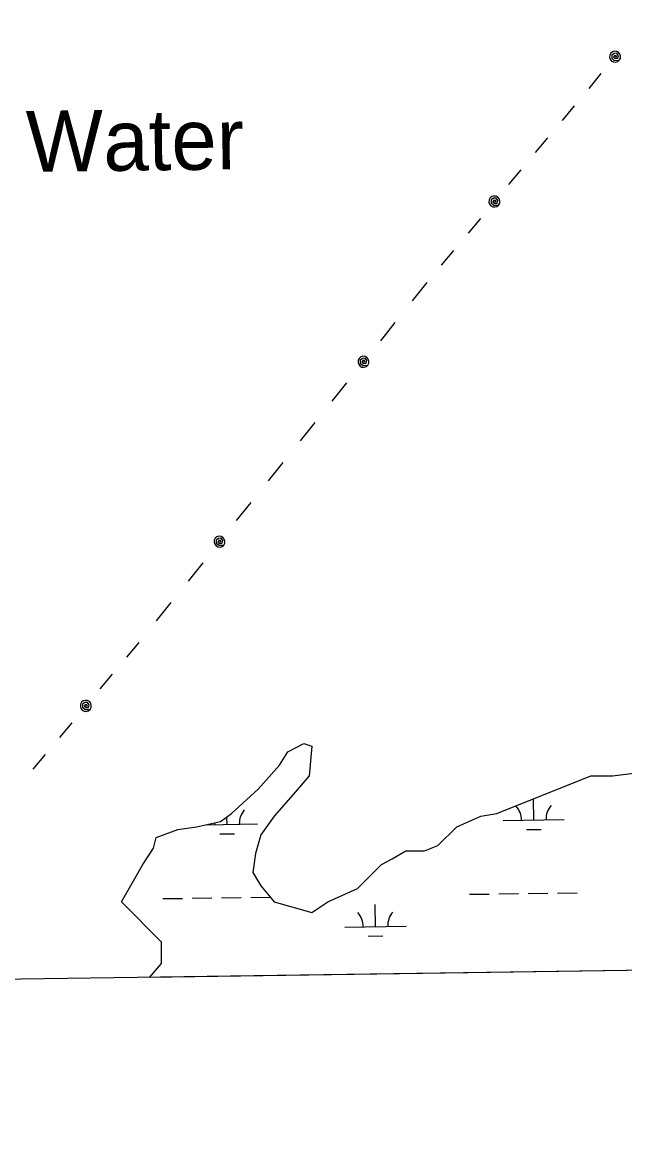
# Model space of a CAD drawing. Extents: x 3775218 to 3813389, y 343470 to 369318.
# Drawn here: x 3796713 to 3797700, y 348893 to 350703 of the extents above; entities that cross this region are included whole.
import ezdxf

# ---------------------------------------------------------------- set-up
doc = ezdxf.new("R2010")
doc.units = 0
for name, color, linetype in [('V-GRID-FRAM', 7, 'Continuous'), ('V-RIVR-IDEN', 7, 'Continuous'), ('V-TOPO-SHOR', 7, 'Continuous'), ('V-UTIL-LINE', 7, 'Continuous'), ('V-WETL-SWMP', 7, 'Continuous')]:
    doc.layers.add(name, color=color, linetype=linetype)

msp = doc.modelspace()

# ---------------------------------------------------------------- linework, layer by layer
at = {"layer": 'V-GRID-FRAM'}
msp.add_lwpolyline([(3779203.7, 367073.2), (3811012.4, 367522), (3811276.9, 349341.6), (3779452.3, 348892.5), (3779203.7, 367073.2)], dxfattribs=at)
at = {"layer": 'V-TOPO-SHOR'}
for p, q in [((3797147.8, 349508.6), (3797174.2, 349521.8)), ((3797174.2, 349521.8), (3797187.3, 349517.4)), ((3797134.6, 349486.7), (3797147.8, 349508.6)), ((3797187.3, 349517.4), (3797182.9, 349469.1)), ((3797099.5, 349447.1), (3797134.6, 349486.7)), ((3797182.9, 349469.1), (3797156.6, 349438.4)), ((3797490.3, 349407.6), (3797643.9, 349469.1)), ((3797643.9, 349469.1), (3797679.1, 349469.1)), ((3797679.1, 349469.1), (3797714.2, 349473.5)), ((3797055.6, 349407.6), (3797099.5, 349447.1)), ((3797156.6, 349438.4), (3797125.9, 349403.2)), ((3796998.5, 349385.6), (3797038.1, 349394.4)), ((3797038.1, 349394.4), (3797055.6, 349407.6)), ((3797125.9, 349403.2), (3797103.9, 349372.5)), ((3797424.4, 349385.6), (3797463.9, 349403.2)), ((3797463.9, 349403.2), (3797490.3, 349407.6)), ((3796932.7, 349368.1), (3796967.8, 349381.2)), ((3796967.8, 349381.2), (3796998.5, 349385.6)), ((3797393.7, 349354.9), (3797424.4, 349385.6)), ((3796928.3, 349350.5), (3796932.7, 349368.1)), ((3797103.9, 349372.5), (3797095.1, 349341.7)), ((3796910.7, 349324.1), (3796928.3, 349350.5)), ((3797095.1, 349341.7), (3797090.7, 349310.9)), ((3797319, 349332.9), (3797341, 349346.1)), ((3797341, 349346.1), (3797371.7, 349346.1)), ((3797371.7, 349346.1), (3797393.7, 349354.9)), ((3796875.6, 349262.6), (3796910.7, 349324.1)), ((3797262, 349284.6), (3797301.5, 349324.1)), ((3797301.5, 349324.1), (3797319, 349332.9)), ((3797090.7, 349310.9), (3797103.9, 349289)), ((3797103.9, 349289), (3797125.9, 349262.6)), ((3797213.7, 349262.6), (3797262, 349284.6)), ((3796941.5, 349196.7), (3796875.6, 349262.6)), ((3797125.9, 349262.6), (3797187.3, 349245)), ((3797187.3, 349245), (3797213.7, 349262.6)), ((3796941.5, 349161.6), (3796941.5, 349196.7)), ((3796921.9, 349139), (3796941.5, 349161.6))]:
    msp.add_line(p, q, dxfattribs=at)
at = {"layer": 'V-UTIL-LINE'}
for points in [[(3797683.6, 350646.7), (3797686.4, 350646.4), (3797685.3, 350648.4), (3797682.5, 350648.6), (3797680.9, 350646.2), (3797683.4, 350643.9), (3797688.1, 350644.2), (3797689.2, 350648.3), (3797686.4, 350652.3), (3797681.9, 350652.1), (3797678.3, 350649.4), (3797678.3, 350644.5), (3797682.3, 350640.8), (3797690.5, 350640.9), (3797692.2, 350644), (3797692.5, 350647.5), (3797691.5, 350650.8), (3797689.3, 350653.6), (3797686.2, 350655.2), (3797682.8, 350655.6), (3797679.4, 350654.6), (3797676.7, 350652.4), (3797675, 350649.3), (3797674.6, 350645.8), (3797675.6, 350642.5), (3797677.8, 350639.7), (3797680.9, 350638.1), (3797684.4, 350637.7), (3797687.8, 350638.7), (3797690.5, 350640.9)], [(3797660.5, 350619), (3797640.4, 350594.9)], [(3797616.8, 350566.5), (3797596.7, 350542.3)], [(3797573, 350513.9), (3797552.9, 350489.8)], [(3797529.3, 350461.4), (3797509.2, 350437.3)], [(3797486.1, 350409.6), (3797489, 350409.4), (3797487.8, 350411.4), (3797485.1, 350411.6), (3797483.5, 350409.1), (3797486, 350406.8), (3797490.6, 350407.1), (3797491.8, 350411.3), (3797489, 350415.2), (3797484.4, 350415.1), (3797480.9, 350412.3), (3797480.9, 350407.5), (3797484.9, 350403.7), (3797493, 350403.9), (3797494.7, 350406.9), (3797495.1, 350410.4), (3797494.1, 350413.8), (3797491.9, 350416.5), (3797488.8, 350418.2), (3797485.3, 350418.6), (3797481.9, 350417.6), (3797479.2, 350415.4), (3797477.5, 350412.3), (3797477.1, 350408.8), (3797478.1, 350405.4), (3797480.4, 350402.7), (3797483.4, 350401), (3797486.9, 350400.7), (3797490.3, 350401.7), (3797493, 350403.9)], [(3797463.1, 350381.9), (3797443, 350357.8)], [(3797419.3, 350329.4), (3797399.2, 350305.3)], [(3797375.6, 350276.9), (3797351.6, 350246.9)], [(3797323.4, 350211.6), (3797299.4, 350181.6)], [(3797271.8, 350147.2), (3797274.7, 350147), (3797273.5, 350149), (3797270.8, 350149.1), (3797269.2, 350146.7), (3797271.8, 350144.4), (3797276.4, 350144.8), (3797277.5, 350149), (3797274.6, 350152.9), (3797270, 350152.6), (3797266.6, 350149.8), (3797266.6, 350145), (3797270.7, 350141.3), (3797278.9, 350141.6), (3797280.5, 350144.7), (3797280.8, 350148.2), (3797279.7, 350151.6), (3797277.5, 350154.2), (3797274.4, 350155.9), (3797270.9, 350156.2), (3797267.5, 350155.1), (3797264.8, 350152.8), (3797263.2, 350149.7), (3797262.9, 350146.2), (3797264, 350142.9), (3797266.2, 350140.2), (3797269.3, 350138.6), (3797272.8, 350138.3), (3797276.2, 350139.3), (3797278.9, 350141.6)], [(3797244.3, 350112.8), (3797220.3, 350082.8)], [(3797192.1, 350047.5), (3797168.1, 350017.5)], [(3797139.9, 349982.2), (3797115.9, 349952.2)], [(3797087.7, 349916.9), (3797063.7, 349887)], [(3797036.2, 349852.5), (3797039.1, 349852.3), (3797037.9, 349854.3), (3797035.1, 349854.5), (3797033.6, 349852), (3797036.1, 349849.7), (3797040.8, 349850.1), (3797041.8, 349854.3), (3797039, 349858.2), (3797034.4, 349857.9), (3797030.9, 349855.1), (3797031, 349850.3), (3797035.1, 349846.6), (3797043.2, 349846.9), (3797044.8, 349850), (3797045.1, 349853.5), (3797044.1, 349856.9), (3797041.8, 349859.6), (3797038.7, 349861.2), (3797035.2, 349861.5), (3797031.9, 349860.4), (3797029.2, 349858.2), (3797027.6, 349855), (3797027.3, 349851.5), (3797028.3, 349848.2), (3797030.6, 349845.5), (3797033.7, 349843.9), (3797037.2, 349843.6), (3797040.5, 349844.7), (3797043.2, 349846.9)], [(3797008.7, 349818.1), (3796984.7, 349788.1)], [(3796956.5, 349752.8), (3796932.5, 349722.8)], [(3796904.3, 349687.6), (3796884.2, 349663.5)], [(3796860.6, 349635.3), (3796840.5, 349611.3)], [(3796817.4, 349583.7), (3796820.3, 349583.4), (3796819.2, 349585.5), (3796816.4, 349585.6), (3796814.8, 349583.2), (3796817.3, 349580.9), (3796822, 349581.2), (3796823.1, 349585.3), (3796820.3, 349589.3), (3796815.8, 349589.1), (3796812.2, 349586.4), (3796812.2, 349581.6), (3796816.2, 349577.8), (3796824.3, 349577.9), (3796826, 349581), (3796826.4, 349584.5), (3796825.4, 349587.9), (3796823.2, 349590.6), (3796820.1, 349592.3), (3796816.6, 349592.7), (3796813.3, 349591.7), (3796810.5, 349589.5), (3796808.9, 349586.4), (3796808.5, 349582.9), (3796809.5, 349579.5), (3796811.7, 349576.8), (3796814.8, 349575.1), (3796818.2, 349574.7), (3796821.6, 349575.7), (3796824.3, 349577.9)], [(3796794.4, 349556.1), (3796774.3, 349532.1)], [(3796750.7, 349503.9), (3796730.6, 349479.8)]]:
    msp.add_lwpolyline(points, dxfattribs=at)
at = {"layer": 'V-WETL-SWMP'}
for p, q in [((3797147.8, 349508.6), (3797174.2, 349521.8)), ((3797174.2, 349521.8), (3797187.3, 349517.4)), ((3797134.6, 349486.7), (3797147.8, 349508.6)), ((3797187.3, 349517.4), (3797182.9, 349469.1)), ((3797099.5, 349447.1), (3797134.6, 349486.7)), ((3797182.9, 349469.1), (3797156.6, 349438.4)), ((3797490.3, 349407.6), (3797643.9, 349469.1)), ((3797643.9, 349469.1), (3797679.1, 349469.1)), ((3797679.1, 349469.1), (3797714.2, 349473.5)), ((3797055.6, 349407.6), (3797099.5, 349447.1)), ((3797156.6, 349438.4), (3797125.9, 349403.2)), ((3797550.5, 349396.6), (3797550, 349431.5)), ((3796998.5, 349385.6), (3797038.1, 349394.4)), ((3797038.1, 349394.4), (3797055.6, 349407.6)), ((3797048.6, 349389.6), (3797048.4, 349402.2)), ((3797125.9, 349403.2), (3797103.9, 349372.5)), ((3797424.4, 349385.6), (3797463.9, 349403.2)), ((3797463.9, 349403.2), (3797490.3, 349407.6)), ((3797500.5, 349395.9), (3797600.5, 349397.3)), ((3796932.7, 349368.1), (3796967.8, 349381.2)), ((3796967.8, 349381.2), (3796998.5, 349385.6)), ((3797014, 349389.1), (3797098.6, 349390.3)), ((3797393.7, 349354.9), (3797424.4, 349385.6)), ((3797538.7, 349381), (3797562.7, 349381.4)), ((3796928.3, 349350.5), (3796932.7, 349368.1)), ((3797036.8, 349374), (3797060.8, 349374.3)), ((3797103.9, 349372.5), (3797095.1, 349341.7)), ((3796910.7, 349324.1), (3796928.3, 349350.5)), ((3797095.1, 349341.7), (3797090.7, 349310.9)), ((3797319, 349332.9), (3797341, 349346.1)), ((3797341, 349346.1), (3797371.7, 349346.1)), ((3797371.7, 349346.1), (3797393.7, 349354.9)), ((3796875.6, 349262.6), (3796910.7, 349324.1)), ((3797262, 349284.6), (3797301.5, 349324.1)), ((3797301.5, 349324.1), (3797319, 349332.9)), ((3797090.7, 349310.9), (3797103.9, 349289)), ((3797103.9, 349289), (3797125.9, 349262.6)), ((3797213.7, 349262.6), (3797262, 349284.6)), ((3796943.5, 349268), (3796975.5, 349268.4)), ((3796991.5, 349268.7), (3797023.5, 349269.1)), ((3797039.5, 349269.3), (3797071.4, 349269.8)), ((3797087.4, 349270), (3797119.3, 349270.5)), ((3797445.3, 349275.1), (3797477.3, 349275.5)), ((3797493.3, 349275.7), (3797525.3, 349276.2)), ((3797541.3, 349276.4), (3797573.3, 349276.9)), ((3797589.3, 349277.1), (3797621.3, 349277.6)), ((3796941.5, 349196.7), (3796875.6, 349262.6)), ((3797125.9, 349262.6), (3797187.3, 349245)), ((3797187.3, 349245), (3797213.7, 349262.6)), ((3797291.5, 349222.2), (3797290.9, 349258.1)), ((3797241.5, 349221.4), (3797341.5, 349222.9)), ((3796941.5, 349161.6), (3796941.5, 349196.7)), ((3797279.7, 349206.6), (3797303.7, 349206.9)), ((3798526.2, 349161.7), (3796921.9, 349139)), ((3796921.9, 349139), (3796941.5, 349161.6))]:
    msp.add_line(p, q, dxfattribs=at)
for centre, start, end in [((3797103.8, 349390.8), 140.0365, 181.5802), ((3797495.2, 349396.3), 0.0365, 41.5802), ((3797605.7, 349397.9), 140.0365, 181.5802), ((3796993.4, 349389.3), 0.0365, 4.9409), ((3797236.2, 349221.8), 0.0365, 41.5802), ((3797346.7, 349223.4), 140.0365, 181.5802)]:
    msp.add_arc(centre, 35.2, start, end, dxfattribs=at)

# ---------------------------------------------------------------- texts
at = {"layer": 'V-RIVR-IDEN'}
msp.add_text('Water', height=100, rotation=0.7588, dxfattribs=at).set_placement((3796720.2, 350457.9))

doc.saveas('drawing.dxf')
